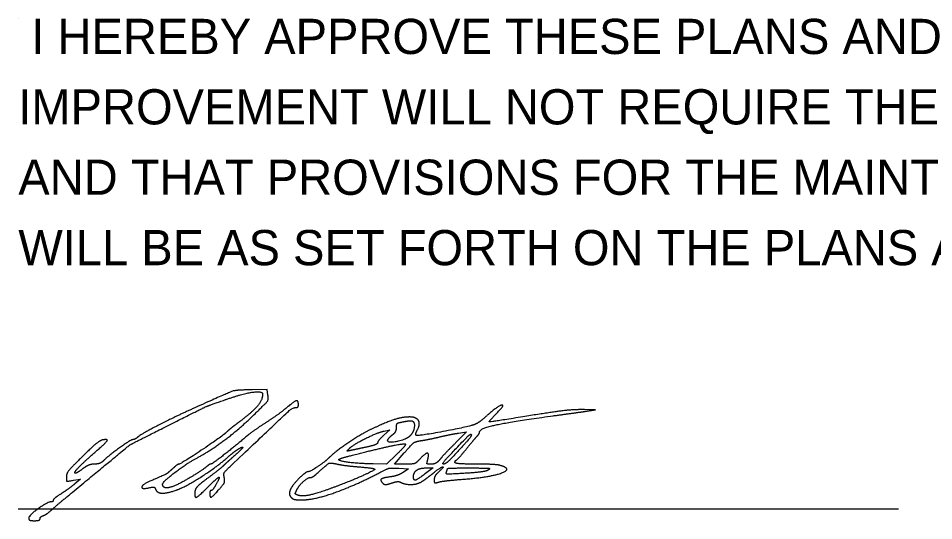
# Model space of a CAD drawing. Extents: x -2.1 to 31.9, y 6.3 to 28.3.
# Drawn here: x 22.462 to 26.102, y 15.223 to 17.221 of the extents above; entities that cross this region are included whole.
import ezdxf

# ---------------------------------------------------------------- set-up
doc = ezdxf.new("R2010")
doc.units = 0
doc.layers.add('SH_Data', color=7, linetype='Continuous')
doc.layers.add('SH_Text', color=7, linetype='Continuous')

msp = doc.modelspace()

# ---------------------------------------------------------------- linework, layer by layer
at = {"layer": 'SH_Data'}
for p, q in [((22.4623, 17.219), (22.4623, 17.219)), ((22.4623, 15.2702), (25.9623, 15.2702))]:
    msp.add_line(p, q, dxfattribs=at)
at = {"layer": 'SH_Text'}
msp.add_line((22.5037, 15.2331), (22.5037, 15.2331), dxfattribs=at)
for points in [[(23.455, 15.7223), (23.4525, 15.7442), (23.3925, 15.7435)], [(24.7162, 15.6576), (24.7575, 15.6634), (24.7198, 15.6644)], [(23.9176, 15.5796), (23.94, 15.5849), (23.9156, 15.5626)], [(24.2125, 15.5711), (24.2451, 15.5758), (24.2013, 15.5324)], [(23.966, 15.4859), (23.9268, 15.4479), (23.8734, 15.4488)], [(23.9987, 15.4479), (23.9578, 15.4479), (23.9971, 15.4925)], [(23.9753, 15.4314), (24.0145, 15.4292), (23.9931, 15.4152)], [(24.0863, 15.4329), (24.1114, 15.4329), (24.0819, 15.4106)], [(22.6819, 15.3837), (22.71, 15.3887), (22.6875, 15.3698)]]:
    msp.add_lwpolyline(points, dxfattribs=at)
for points in [[(23.3925, 15.7435), (23.33, 15.7428), (23.3036, 15.7346), (23.1675, 15.6734)], [(23.295, 15.7074), (23.359, 15.7293), (23.4337, 15.7393), (23.4337, 15.726)], [(23.4337, 15.726), (23.4337, 15.702), (23.3887, 15.6507), (23.3296, 15.6072)], [(23.085, 15.6152), (23.1972, 15.6715), (23.2228, 15.6827), (23.295, 15.7074)], [(23.3949, 15.6398), (23.4489, 15.6922), (23.4571, 15.7035), (23.455, 15.7223)], [(23.5762, 15.6842), (23.5762, 15.7022), (23.5587, 15.6973), (23.527, 15.6705)], [(23.1675, 15.6734), (23.0873, 15.6374), (22.9514, 15.5678), (22.9381, 15.556)], [(23.3099, 15.4437), (23.5313, 15.6533), (23.5532, 15.6729), (23.5669, 15.6729)], [(23.527, 15.6705), (23.5107, 15.6568), (23.4739, 15.6303), (23.445, 15.6117)], [(23.5669, 15.6729), (23.572, 15.6729), (23.5762, 15.678), (23.5762, 15.6842)], [(24.363, 15.6485), (24.3998, 15.6854), (24.3703, 15.68), (24.3274, 15.6421)], [(24.7198, 15.6644), (24.6754, 15.6656), (24.5914, 15.656), (24.4598, 15.6346)], [(24.5895, 15.6401), (24.6365, 15.6465), (24.6935, 15.6544), (24.7162, 15.6576)], [(23.1716, 15.472), (23.2253, 15.5003), (23.34, 15.5866), (23.3949, 15.6398)], [(24.0188, 15.6354), (23.9913, 15.6354), (23.9295, 15.6163), (23.8741, 15.5906)], [(23.9662, 15.5936), (23.9662, 15.6071), (23.9715, 15.6121), (23.9897, 15.6157)], [(23.9897, 15.6157), (24.0026, 15.6183), (24.0177, 15.6204), (24.0234, 15.6204)], [(24.0489, 15.5832), (24.0617, 15.6071), (24.0454, 15.6354), (24.0188, 15.6354)], [(24.0234, 15.6204), (24.0384, 15.6204), (24.0364, 15.5776), (24.0206, 15.5609)], [(24.3274, 15.6421), (24.3082, 15.6251), (24.2857, 15.6088), (24.2775, 15.6057)], [(24.2962, 15.575), (24.2962, 15.5895), (24.4188, 15.6167), (24.5895, 15.6401)], [(24.4598, 15.6346), (24.3394, 15.6151), (24.3308, 15.6163), (24.363, 15.6485)], [(22.6762, 15.335), (22.9008, 15.5209), (22.9104, 15.5275), (23.085, 15.6152)], [(23.3296, 15.6072), (23.3147, 15.5962), (23.2965, 15.5813), (23.2893, 15.574)], [(23.445, 15.6117), (23.4161, 15.593), (23.3824, 15.5691), (23.37, 15.5584)], [(23.8741, 15.5906), (23.832, 15.5711), (23.7235, 15.4988), (23.6978, 15.4731)], [(23.7787, 15.5102), (23.7931, 15.5251), (23.8882, 15.5726), (23.9176, 15.5796)], [(23.9526, 15.5665), (23.9601, 15.5719), (23.9662, 15.5841), (23.9662, 15.5936)], [(24.0442, 15.5625), (24.0419, 15.5648), (24.044, 15.5741), (24.0489, 15.5832)], [(24.2775, 15.6057), (24.2501, 15.5956), (24.0484, 15.5583), (24.0442, 15.5625)], [(22.7966, 15.5441), (22.7885, 15.5427), (22.7531, 15.5134), (22.7178, 15.4788)], [(22.7869, 15.5125), (22.8146, 15.5367), (22.8179, 15.5475), (22.7966, 15.5441)], [(22.919, 15.5454), (22.9103, 15.5454), (22.8206, 15.4816), (22.8016, 15.4618)], [(22.9381, 15.556), (22.9316, 15.5502), (22.923, 15.5454), (22.919, 15.5454)], [(23.2893, 15.574), (23.2744, 15.5592), (23.1077, 15.4479), (23.1003, 15.4479)], [(23.37, 15.5584), (23.3253, 15.52), (23.2326, 15.4479), (23.2279, 15.4479)], [(23.9156, 15.5626), (23.9022, 15.5503), (23.8912, 15.5369), (23.8912, 15.5328)], [(24.0206, 15.5609), (24.0042, 15.5437), (23.9232, 15.5303), (23.9329, 15.5465)], [(23.9329, 15.5465), (23.9363, 15.5521), (23.9452, 15.5611), (23.9526, 15.5665)], [(24.0669, 15.5419), (24.0837, 15.5445), (24.116, 15.5511), (24.1387, 15.5565)], [(24.1387, 15.5565), (24.1614, 15.5619), (24.1946, 15.5685), (24.2125, 15.5711)], [(24.1541, 15.4479), (24.1462, 15.4479), (24.1676, 15.4731), (24.2386, 15.5473)], [(24.2632, 15.5659), (24.2667, 15.5624), (24.2429, 15.5335), (24.1902, 15.4771)], [(24.2386, 15.5473), (24.2502, 15.5595), (24.2613, 15.5679), (24.2632, 15.5659)], [(24.2437, 15.5079), (24.2622, 15.5306), (24.2816, 15.5536), (24.2868, 15.5591)], [(24.2868, 15.5591), (24.292, 15.5645), (24.2962, 15.5717), (24.2962, 15.575)], [(22.6869, 15.4123), (22.6832, 15.416), (22.7301, 15.463), (22.7869, 15.5125)], [(23.2987, 15.4781), (23.3132, 15.4908), (23.3313, 15.5047), (23.339, 15.5091)], [(23.339, 15.5091), (23.3598, 15.5207), (23.3472, 15.5029), (23.3146, 15.4747)], [(23.7862, 15.5026), (23.7694, 15.499), (23.7686, 15.4998), (23.7787, 15.5102)], [(23.8481, 15.516), (23.8244, 15.5108), (23.7965, 15.5048), (23.7862, 15.5026)], [(23.7915, 15.4836), (23.8883, 15.5084), (23.9979, 15.5313), (24.0017, 15.5275)], [(23.8912, 15.5328), (23.8912, 15.5287), (23.8718, 15.5211), (23.8481, 15.516)], [(24.0017, 15.5275), (24.0036, 15.5255), (23.9876, 15.5068), (23.966, 15.4859)], [(23.9971, 15.4925), (24.0294, 15.5293), (24.0416, 15.5379), (24.0669, 15.5419)], [(24.2013, 15.5324), (24.1772, 15.5086), (24.1499, 15.4798), (24.1407, 15.4685)], [(24.2044, 15.4642), (24.2074, 15.4655), (24.2252, 15.4852), (24.2437, 15.5079)], [(22.7178, 15.4788), (22.6715, 15.4334), (22.6537, 15.4108), (22.6537, 15.3974)], [(23.0362, 15.368), (23.0362, 15.3775), (23.132, 15.451), (23.1716, 15.472)], [(23.0895, 15.3442), (23.1265, 15.357), (23.2531, 15.438), (23.2987, 15.4781)], [(23.3146, 15.4747), (23.3, 15.462), (23.2824, 15.4462), (23.2755, 15.4394)], [(23.6978, 15.4731), (23.6825, 15.4578), (23.6232, 15.4179), (23.6158, 15.4179)], [(23.7367, 15.465), (23.7347, 15.467), (23.7594, 15.4753), (23.7915, 15.4836)], [(24.0906, 15.4667), (24.0969, 15.4914), (24.0808, 15.4913), (24.0573, 15.4665)], [(24.1902, 15.4771), (24.1752, 15.461), (24.159, 15.4479), (24.1541, 15.4479)], [(22.7654, 15.4479), (22.7524, 15.4479), (22.7316, 15.4394), (22.7168, 15.4281)], [(22.8016, 15.4618), (22.7942, 15.4542), (22.7779, 15.4479), (22.7654, 15.4479)], [(23.1003, 15.4479), (23.0977, 15.4479), (23.0865, 15.4395), (23.0754, 15.4292)], [(23.214, 15.4403), (23.1994, 15.428), (23.1516, 15.3975), (23.1148, 15.377)], [(23.2279, 15.4479), (23.2253, 15.4479), (23.219, 15.4445), (23.214, 15.4403)], [(23.2755, 15.4394), (23.2687, 15.4327), (23.2442, 15.4133), (23.2211, 15.3962)], [(23.2814, 15.3942), (23.2785, 15.4094), (23.2843, 15.4195), (23.3099, 15.4437)], [(23.6479, 15.4087), (23.6921, 15.4489), (23.703, 15.454), (23.7319, 15.4478)], [(23.7319, 15.4478), (23.7473, 15.4445), (23.7881, 15.4394), (23.8225, 15.4365)], [(23.8734, 15.4488), (23.8181, 15.4498), (23.7429, 15.4587), (23.7367, 15.465)], [(23.8225, 15.4365), (23.8569, 15.4336), (23.8822, 15.4288), (23.8788, 15.4259)], [(24.0573, 15.4665), (24.0427, 15.4511), (24.0326, 15.4479), (23.9987, 15.4479)], [(24.1049, 15.4479), (24.0884, 15.4479), (24.0866, 15.4504), (24.0906, 15.4667)], [(24.1407, 15.4685), (24.1304, 15.4559), (24.1165, 15.4479), (24.1049, 15.4479)], [(24.1073, 15.4085), (24.1399, 15.4348), (24.1591, 15.4394), (24.1313, 15.4142)], [(24.1987, 15.4548), (24.1987, 15.4586), (24.2013, 15.4628), (24.2044, 15.4642)], [(24.2794, 15.4478), (24.235, 15.4479), (24.1987, 15.451), (24.1987, 15.4548)], [(24.2287, 15.3876), (24.34, 15.3962), (24.4286, 15.4293), (24.3772, 15.4431)], [(24.3772, 15.4431), (24.3677, 15.4456), (24.3237, 15.4478), (24.2794, 15.4478)], [(22.6537, 15.3974), (22.6537, 15.38), (22.6556, 15.3791), (22.6819, 15.3837)], [(22.7168, 15.4281), (22.7025, 15.4172), (22.689, 15.4101), (22.6869, 15.4123)], [(23.0754, 15.4292), (23.0561, 15.4113), (23.0417, 15.4034), (22.9856, 15.3796)], [(23.6158, 15.4179), (23.6048, 15.4179), (23.5477, 15.3595), (23.5425, 15.3428)], [(23.5868, 15.3054), (23.6364, 15.3054), (23.7957, 15.3605), (23.893, 15.4112)], [(23.6254, 15.3951), (23.6298, 15.3953), (23.6399, 15.4014), (23.6479, 15.4087)], [(23.8788, 15.4259), (23.8693, 15.4178), (23.7674, 15.3739), (23.7037, 15.3506)], [(23.893, 15.4112), (23.9279, 15.4294), (23.9435, 15.4333), (23.9753, 15.4314)], [(23.9425, 15.3973), (23.9111, 15.3931), (23.9, 15.3836), (23.9122, 15.3714)], [(23.9931, 15.4152), (23.9813, 15.4075), (23.9585, 15.3994), (23.9425, 15.3973)], [(24.0337, 15.398), (24.0337, 15.4154), (24.0601, 15.4329), (24.0863, 15.4329)], [(24.0819, 15.4106), (24.05, 15.3864), (24.0337, 15.3822), (24.0337, 15.398)], [(24.06, 15.3748), (24.0682, 15.379), (24.0895, 15.3941), (24.1073, 15.4085)], [(24.1313, 15.4142), (24.123, 15.4067), (24.1162, 15.394), (24.1162, 15.3859)], [(24.239, 15.4113), (24.1754, 15.4074), (24.1617, 15.4084), (24.1649, 15.4166)], [(24.1649, 15.4166), (24.167, 15.4221), (24.1687, 15.428), (24.1687, 15.4298)], [(24.1687, 15.4298), (24.1687, 15.4315), (24.2084, 15.4328), (24.2569, 15.4327)], [(24.331, 15.4243), (24.3233, 15.4198), (24.2819, 15.414), (24.239, 15.4113)], [(24.2569, 15.4327), (24.3239, 15.4325), (24.3416, 15.4305), (24.331, 15.4243)], [(22.6875, 15.3698), (22.6751, 15.3594), (22.6506, 15.3417), (22.6331, 15.3304)], [(22.9856, 15.3796), (22.9544, 15.3663), (22.9522, 15.3472), (22.9828, 15.354)], [(23.1148, 15.377), (23.0777, 15.3562), (23.0362, 15.3515), (23.0362, 15.368)], [(23.2211, 15.3962), (23.1812, 15.3668), (23.1637, 15.3461), (23.1637, 15.3284)], [(23.2137, 15.3542), (23.252, 15.3931), (23.2661, 15.3978), (23.2478, 15.3655)], [(23.2478, 15.3655), (23.2407, 15.3531), (23.2324, 15.343), (23.2294, 15.343)], [(23.2611, 15.3477), (23.2788, 15.3678), (23.2841, 15.38), (23.2814, 15.3942)], [(23.5698, 15.3454), (23.5794, 15.3641), (23.6137, 15.3947), (23.6254, 15.3951)], [(23.9122, 15.3714), (23.9174, 15.3662), (23.9284, 15.3666), (23.9466, 15.3726)], [(23.9466, 15.3726), (23.9614, 15.3775), (23.9773, 15.3791), (23.9821, 15.3761)], [(23.9821, 15.3761), (23.9962, 15.3674), (24.0438, 15.3666), (24.06, 15.3748)], [(24.1162, 15.3859), (24.1162, 15.3741), (24.1196, 15.3722), (24.1331, 15.3763)], [(24.1331, 15.3763), (24.1424, 15.3792), (24.1854, 15.3842), (24.2287, 15.3876)], [(22.5937, 15.2652), (22.604, 15.2745), (22.6412, 15.3059), (22.6762, 15.335)], [(22.6331, 15.3304), (22.6156, 15.3192), (22.6012, 15.3072), (22.6012, 15.3039)], [(22.9828, 15.354), (22.9985, 15.3574), (23.0055, 15.3555), (23.0088, 15.347)], [(23.0088, 15.347), (23.0142, 15.333), (23.053, 15.3316), (23.0895, 15.3442)], [(23.1637, 15.3284), (23.1637, 15.3122), (23.1812, 15.3213), (23.2137, 15.3542)], [(23.2237, 15.3317), (23.2237, 15.3135), (23.2355, 15.3186), (23.2611, 15.3477)], [(23.2294, 15.343), (23.2263, 15.3429), (23.2237, 15.3378), (23.2237, 15.3317)], [(23.5425, 15.3428), (23.5397, 15.3342), (23.5415, 15.3223), (23.5465, 15.3163)], [(23.5707, 15.3253), (23.5636, 15.3282), (23.5634, 15.333), (23.5698, 15.3454)], [(23.7037, 15.3506), (23.6464, 15.3296), (23.5875, 15.3183), (23.5707, 15.3253)], [(22.5936, 15.2979), (22.5794, 15.2979), (22.5037, 15.2433), (22.5037, 15.2331)], [(22.6012, 15.3039), (22.6012, 15.3006), (22.5978, 15.2979), (22.5936, 15.2979)], [(23.5465, 15.3163), (23.5518, 15.31), (23.5686, 15.3054), (23.5868, 15.3054)], [(22.5619, 15.2433), (22.5691, 15.246), (22.5834, 15.2558), (22.5937, 15.2652)], [(22.5037, 15.2331), (22.5037, 15.2268), (22.5123, 15.2229), (22.5262, 15.2229)], [(22.5262, 15.2229), (22.5386, 15.2229), (22.5487, 15.2264), (22.5487, 15.2306)], [(22.5487, 15.2306), (22.5487, 15.2349), (22.5546, 15.2406), (22.5619, 15.2433)]]:
    msp.add_open_spline(points, degree=2, dxfattribs=at)

# ---------------------------------------------------------------- texts
at = {"layer": 'SH_Data'}
for s, p in [(' I HEREBY APPROVE THESE PLANS AND DECLARE THAT THE MAKING OF THIS', (22.4623, 17.079)), ('IMPROVEMENT WILL NOT REQUIRE THE CLOSING TO TRAFFIC OF THE HIGHWAY', (22.4623, 16.799)), ('AND THAT PROVISIONS FOR THE MAINTENANCE AND SAFETY OF TRAFFIC', (22.4623, 16.519)), ('WILL BE AS SET FORTH ON THE PLANS AND ESTIMATES.', (22.4623, 16.239))]:
    msp.add_text(s, height=0.14, dxfattribs=at).set_placement(p)

doc.saveas('drawing.dxf')
